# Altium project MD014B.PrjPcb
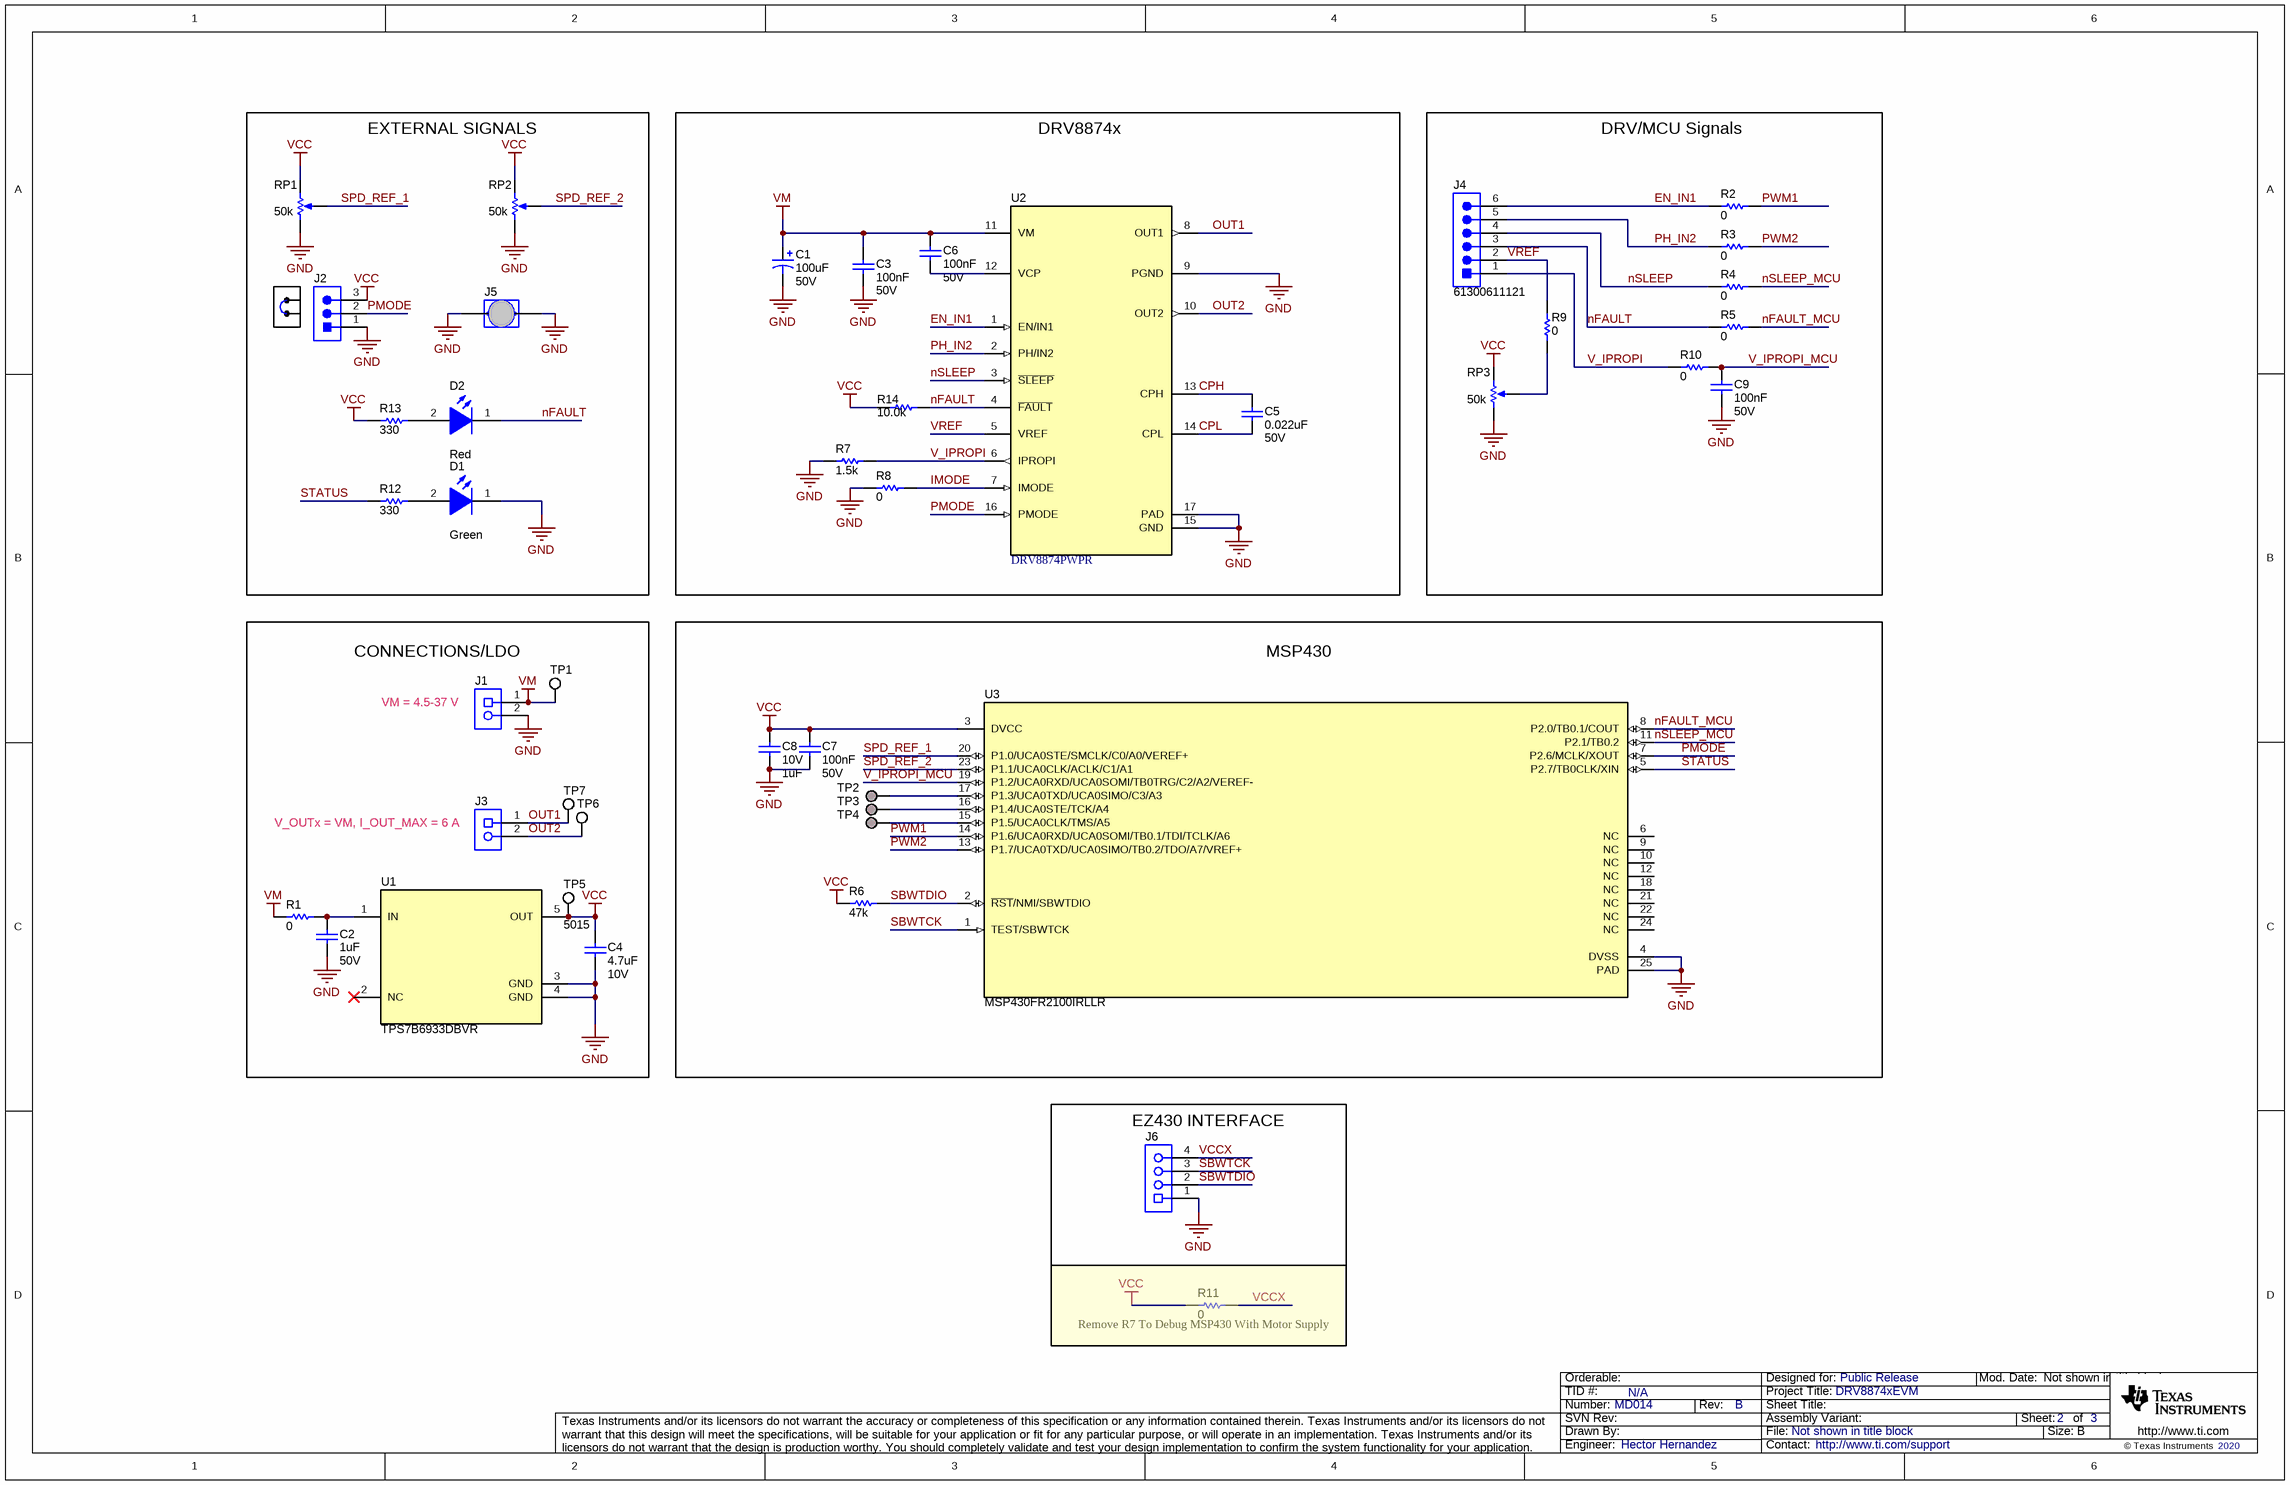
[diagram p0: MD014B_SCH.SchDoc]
CopyrightYear: 2020; PCB_Layout: Hector Hernandez; PCB_Rev: B; PRJ_Customer: Public Release; PRJ_Engineer: Hector Hernandez; PRJ_Number: MD014; PRJ_Title: DRV8874xEVM; SCH_Rev: B; TechSupport: http://www.ti.com/support; TID: N/A
2 sheets, 64 parts. Net scope: global (net labels, ports and power ports of the same name join across sheets).
Board file: MD014B_PCB.PcbDoc
Sheets:
  MD014B_SCH.SchDoc
  MD014B_Hardware.SchDoc

## Sheet MD014B_SCH.SchDoc
size 431 x 279 mm; Date: Not shown in title block; ApprovedBy: Not shown in title block; CheckedBy: Not shown in title block; Author: Not shown in title block; CompanyName: Not shown in title block; Engineer: Not shown in title block; Organization: Not shown in title block; Address1: Not shown in title block; Address2: Not shown in title block; Address3: Not shown in title block; Address4: Not shown in title block; DocumentNumber: 1; Revision: Use project parameter SCH_Rev; SheetNumber: 2; SheetTotal: 3; PageSetup: Record=PageOptions¦CenterHorizontal=True¦CenterVertical=True¦PrintScale=1.00¦XCorrection=1.00¦YCorrection=1.00¦PrintKind=0¦BorderSize=5000000¦LeftOffset=0¦BottomOffset=0¦Orientation=2¦PaperLength=1000¦PaperWidth=1000¦Scale=100¦PaperSource=15¦PrintQuality=600¦MediaType=1¦DitherType=10¦PaperKind=Letter¦PrintScaleMode=1

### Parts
C1  ValueDisplayed: 100uF  VDC_V: 50V  [BT_1000x1250]  (hidden comment: UBT1H101MPD1TD)
C2  ValueDisplayed: 1uF  VDC_V: 50V  [0805L]  (hidden comment: 885012207103)
C3  Cap_F: 100nF  VDC_V: 50V  [0603L]  (hidden comment: 885012206095)
C4  ValueDisplayed: 4.7uF  VDC_V: 10V  [0603L]  (hidden comment: C0603C475K8PACTU)
C5  ValueDisplayed: 0.022uF  VDC_V: 50V  [0603L]  (hidden comment: 885012206091)
C6  Cap_F: 100nF  VDC_V: 50V  [0603L]  (hidden comment: 885012206095)
C7  Cap_F: 100nF  VDC_V: 50V  [0603L]  (hidden comment: 885012206095)
C8  VDC_V: 10V  ValueDisplayed: 1uF  [0603L]  (hidden comment: 885012206026)
C9  Cap_F: 100nF  VDC_V: 50V  [0603L]  (hidden comment: 885012206095)
D1  value Green  [WL-SMCW_GREEN]  (hidden comment: 150060VS75000)
D2  value Red  [WL-SMCW_RED]  (hidden comment: 150060RS75000)
J1  CMP-0054828-1  [Wurth_691101710002]  (value not drawn)
J2  61300311121  [WURTH_61300311121]  (value not drawn)
J3  CMP-0054828-1  [Wurth_691101710002]  (value not drawn)
J4  61300611121  [WURTH_61300611121]
J5  D3082-05  [Harwin_D3082-05]  (value not drawn)
J6  851-43-004-20-001000  [CONN_851-43-004-20-001000]  (value not drawn)
R1  ValueDisplayed: 0  [0603L]  (hidden comment: ERJ-3GEY0R00V)
R2  ValueDisplayed: 0  [0603L]  (hidden comment: ERJ-3GEY0R00V)
R3  ValueDisplayed: 0  [0603L]  (hidden comment: ERJ-3GEY0R00V)
R4  ValueDisplayed: 0  [0603L]  (hidden comment: ERJ-3GEY0R00V)
R5  ValueDisplayed: 0  [0603L]  (hidden comment: ERJ-3GEY0R00V)
R6  ValueDisplayed: 47k  [0603L]  (hidden comment: CRCW060347K0JNEA)
R7  ValueDisplayed: 1.5k  [0603L]  (hidden comment: CRCW06031K50JNEA)
R8  ValueDisplayed: 0  [0603L]  (hidden comment: ERJ-3GEY0R00V)
R9  ValueDisplayed: 0  [0603L]  (hidden comment: ERJ-3GEY0R00V)
R10  ValueDisplayed: 0  [0603L]  (hidden comment: ERJ-3GEY0R00V)
R11  ValueDisplayed: 0  [0603L]  (hidden comment: ERJ-3GEY0R00V)
R12  ValueDisplayed: 330  [0603L]  (hidden comment: CRCW0603330RJNEA)
R13  ValueDisplayed: 330  [0603L]  (hidden comment: CRCW0603330RJNEA)
R14  ValueDisplayed: 10.0k  [0603L]  (hidden comment: ERA-3ARW103V)
RP1  value 50k  [Bourns_3352T]  (hidden comment: 3352T-1-503LF)
RP2  value 50k  [Bourns_3352T]  (hidden comment: 3352T-1-503LF)
RP3  value 50k  [Bourns_3352T]  (hidden comment: 3352T-1-503LF)
SH-J1  60900213421  [Wurth_60900213421]  (value not drawn)
TP1  5016  [Testpoint_Keystone_Compact]  (value not drawn)
TP2  TP_H0.45P0.75  [TP_H045P075]  (value not drawn)  (no BOM)
TP3  TP_H0.45P0.75  [TP_H045P075]  (value not drawn)  (no BOM)
TP4  TP_H0.45P0.75  [TP_H045P075]  (value not drawn)  (no BOM)
TP5  5015  [Testpoint_Keystone_Compact]
TP6  5016  [Testpoint_Keystone_Compact]  (value not drawn)
TP7  5016  [Testpoint_Keystone_Compact]  (value not drawn)
U1  TPS7B6933DBVR  [DBV0005A_N]
U2  DRV8874PWPR  [PWP0016J_N]
U3  MSP430FR2100IRLLR  [RLL0024A]

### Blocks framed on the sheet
EXTERNAL SIGNALS: D1 D2 J2 J5 R12 R13 RP1 RP2 SH-J1
DRV8874x: C1 C3 C5 C6 R7 R8 R14 U2
DRV/MCU Signals: C9 J4 R2-R5 R9 R10 RP3
CONNECTIONS/LDO: C2 C4 J1 J3 R1 TP1 TP5-TP7 U1
MSP430: C7 C8 R6 TP2-TP4 U3
EZ430 INTERFACE: J6
Remove R7 To Debug MSP430 With Motor Supply: R11

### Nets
GND: C1.2(-) C2.2 C3.2 C4.2 C7.2 C8.2 C9.2 D1.1(K) J1.2 J2.1 J5.1 J5.2 J6.1 R7.1 R8.1 RP1.1(CCW) RP2.1(CCW) RP3.1(CCW) U1.3(GND) U1.4(GND) U2.9(PGND) U2.15(GND) U2.17(PAD) U3.4(DVSS) U3.25(PAD)
VCC: C4.1 C7.1 C8.1 J2.3 R6.1 R11.1 R13.2 R14.1 RP1.3(CW) RP2.3(CW) RP3.3(CW) TP5.1 U1.5(OUT) U3.3(DVCC)
VM: C1.1(+) C3.1 C6.1 J1.1 R1.1 TP1.1 U2.11(VM)
CPH: C5.1 U2.13(CPH)
CPL: C5.2 U2.14(CPL)
EN_IN1: J4.6 R2.1 U2.1(EN/IN1)
IMODE: R8.2 U2.7(IMODE)
nFAULT: D2.1(K) J4.3 R5.1 R14.2 U2.4(~{FAULT})
nFAULT_MCU: R5.2 U3.8(P2.0/TB0.1/COUT)
nSLEEP: J4.4 R4.1 U2.3(~{SLEEP})
nSLEEP_MCU: R4.2 U3.11(P2.1/TB0.2)
OUT1: J3.1 TP7.1 U2.8(OUT1)
OUT2: J3.2 TP6.1 U2.10(OUT2)
PH_IN2: J4.5 R3.1 U2.2(PH/IN2)
PMODE: J2.2 U2.16(PMODE) U3.7(P2.6/MCLK/XOUT)
PWM1: R2.2 U3.14(P1.6/UCA0RXD/UCA0SOMI/TB0.1/TDI/TCLK/A6)
PWM2: R3.2 U3.13(P1.7/UCA0TXD/UCA0SIMO/TB0.2/TDO/A7/VREF+)
SBWTCK: J6.3 U3.1(TEST/SBWTCK)
SBWTDIO: J6.2 R6.2 U3.2(~{RST}/NMI/SBWTDIO)
SPD_REF_1: RP1.2(WIPER) U3.20(P1.0/UCA0STE/SMCLK/C0/A0/VEREF+)
SPD_REF_2: RP2.2(WIPER) U3.23(P1.1/UCA0CLK/ACLK/C1/A1)
STATUS: R12.2 U3.5(P2.7/TB0CLK/XIN)
V_IPROPI: J4.1 R7.2 R10.1 U2.6(IPROPI)
V_IPROPI_MCU: C9.1 R10.2 U3.19(P1.2/UCA0RXD/UCA0SOMI/TB0TRG/C2/A2/VEREF-)
VCCX: J6.4 R11.2
VREF: J4.2 R9.1 U2.5(VREF)
NetC2_1: C2.1 R1.2 U1.1(IN)
NetC6_2: C6.2 U2.12(VCP)
NetD1_2: D1.2(A) R12.1
NetD2_2: D2.2(A) R13.1
NetR9_2: R9.2 RP3.2(WIPER)
NetTP2_1: TP2.1 U3.17(P1.3/UCA0TXD/UCA0SIMO/C3/A3)
NetTP3_1: TP3.1 U3.16(P1.4/UCA0STE/TCK/A4)
NetTP4_1: TP4.1 U3.15(P1.5/UCA0CLK/TMS/A5)

Not connected (* = marked no-connect by the designer): U1 2(NC)*; U3 6(NC) 9(NC) 10(NC) 12(NC) 18(NC) 21(NC) 22(NC) 24(NC)

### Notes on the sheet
- (near J1) VM = 4.5-37 V
- (near J3) V_OUTx = VM, I_OUT_MAX = 6 A

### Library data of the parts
C1 = CMP-0009918-2: CAP, AL, 100 uF, 50 V, +/- 20%, TH; Manufacturer: Nichicon; Polarized: Y; CompType: Capacitor; Value: 100uF; U/M: EA; Cap_F: 100µF; Value1: Unknown; IRMS_A: 5.55dA; TaMin_C: -40°C; TaMax_C: 125°C; Cap_Case: 10x12.5mm; SizeAreaWB_mm2: 144; SizeArea_mm2: 100; SizeX_mm: 10; SizeZ_mm: 14.5; AEC Category: Q200; AEC Qualified: N
C2 = CMP-0007696-2: CAP, CERM, 1 uF, 50 V, +/- 10%, X7R, 0805; Manufacturer: Wurth Elektronik; Polarized: N; CompType: Capacitor; Value: 1uF; U/M: EA; Cap_F: 1µF; Value1: Unknown; TaMin_C: -55°C; TaMax_C: 125°C; Cap_Case: 0805; SizeArea_mm2: 2.5; SizeAreaWB_mm2: 6.75; SizeX_mm: 2; SizeY_mm: 1.25; SizeZ_mm: 1.45; AEC Category: Q200
C3 C6 C7 C9 = CMP-0006837-4: CAP, CERM, 0.1 uF, 50 V, +/- 10%, X7R, 0603; Manufacturer: Wurth Elektronik; Polarized: N; Value: 0.1uF; U/M: EA; Value1: Unknown; TaMin_C: -55°C; TaMax_C: 125°C; Cap_Case: 0603; SizeArea_mm2: 1.28; SizeAreaWB_mm2: 4.68; SizeX_mm: 1.6; SizeY_mm: 0.8; SizeZ_mm: 1; AEC Category: Q200
C4 = CMP-0006949-5: CAP, CERM, 4.7 uF, 10 V, +/- 10%, X5R, 0603; Manufacturer: Kemet; Polarized: N; CompType: Capacitor; Value: 4.7uF; U/M: EA; Cap_F: 4.7µF; ESR_ohm: 6m; Value1: 0.006 ohm; IRMS_A: 7.24A; TaMin_C: -55°C; TaMax_C: 85°C; Cap_Case: 0603; SizeArea_mm2: 1.28; SizeAreaWB_mm2: 4.68; SizeX_mm: 1.6; SizeY_mm: 0.8; SizeZ_mm: 1; AEC Category: Q200
C5 = CMP-0006836-4: CAP, CERM, 0.022 uF, 50 V, +/- 10%, X7R, 0603; Manufacturer: Wurth Elektronik; Polarized: N; U/M: EA; Cap_F: 22nF; Value1: Unknown; TaMin_C: -55°C; TaMax_C: 125°C; Cap_Case: 0603; SizeArea_mm2: 1.28; SizeAreaWB_mm2: 4.68; SizeX_mm: 1.6; SizeY_mm: 0.8; SizeZ_mm: 1; AEC Category: Q200
C8 = CMP-0064932-4: CAP, CERM, 1 uF, 10 V,+/- 10%, X7R, 0603; Manufacturer: Wurth Elektronik; TaMin_C: -55°C; Polarized: N; SizeAreaWB_mm2: 4.68; Value1: Unknown; U/M: EA; Value: 1uF; TaMax_C: 125°C; SizeZ_mm: 1; SizeX_mm: 1.6; SizeY_mm: 0.8; Cap_Case: 0603; SizeArea_mm2: 1.28; CompType: Capacitor; Cap_F: 1µF; AEC Category: Q200
D1 = CMP-0002894-1: LED, Green, SMD; Manufacturer: Wurth Elektronik; Type: AlInGaP; Vf_V: 2V; Io_A: 20mA; Value1: W; U/M: EA
D2 = CMP-0002947-2: LED, Red, SMD; Manufacturer: Wurth Elektronik; Type: AlInGaP; Vf_V: 2V; Io_A: 30mA; Vr_V: 5V; Tjmax_C: 85°C; Power_TotalModule: 72mW; Value1: 0.072W; Angle: 140; U/M: EA
J1 J3 = CMP-0054828-1: Terminal Block, 5 mm, 2x1, Tin, TH; PartNumber: 691 101 710 002; Manufacturer: Wurth Elektronik; CNHeader: FALSE; Green_Lifecycle: Active; Green_REACh: Passed; CT: TRUE
J2 = CMP-0054796-1: Header, 2.54 mm, 3x1, Gold, TH; Manufacturer: Wurth Elektronik; Green_Lifecycle: Active; Green_REACh: Passed; CNHeader: TRUE; CT: FALSE
J4 = CMP-0054801-1: Header, 2.54 mm, 6x1, Gold, TH; Manufacturer: Wurth Elektronik; CNHeader: TRUE; CT: FALSE
J5 = CMP-0075110-1: 1mm Uninsulated Shorting Plug, 10.16mm spacing, TH; Manufacturer: Harwin; CompType: Jumper Wire; Green_Lifecycle: Active; Green_REACh: Passed; CNHeader: False
J6 = CMP-0055060-1: SOCKET .050" GRID SIP 4 POS R/A, TH; Manufacturer: Mill-Max; CompType: Socket Strip; CNHeader: FALSE; CT: TRUE; Gender: Female; Green_Lifecycle: Active; Green_REACh: Passed
R1-R5 R8-R11 = CMP-0025874-3: RES, 0, 5%, 0.1 W, 0603; Manufacturer: Panasonic; Value: 0; Value_Code: 0000; Power_W: 100mW; Value2: 0.1W; VDC_V: 50V; TempCo: 600 ppm/C; EIA_Code: E24; U/M: EA; SizeArea_mm2: 1.28; SizeX_mm: 1.6; SizeY_mm: 0.8; SizeZ_mm: 1; AEC Category: Q200
R6 = CMP-0025814-4: RES, 47 k, 5%, 0.1 W, AEC-Q200 Grade 0, 0603; Manufacturer: Vishay-Dale; Value: 47k; Value_Code: 47k0; Power_W: 100mW; Value2: 0.1W; VDC_V: 75V; TempCo: 200 ppm/C; EIA_Code: E24; AEC Category: Q200; AEC Grade: 0; AEC Qualified: Y; SizeArea_mm2: 1.28; SizeX_mm: 1.6; SizeY_mm: 0.8; SizeZ_mm: 1
R7 = CMP-0025733-4: RES, 1.5 k, 5%, 0.1 W, AEC-Q200 Grade 0, 0603; Manufacturer: Vishay-Dale; Value: 1.5k; Value_Code: 1k50; Power_W: 100mW; Value2: 0.1W; VDC_V: 75V; TempCo: 200 ppm/C; SizeArea_mm2: 1.28; SizeX_mm: 1.6; SizeY_mm: 0.8; SizeZ_mm: 1; EIA_Code: E24; AEC Category: Q200; AEC Qualified: Y; AEC Grade: 0
R12 R13 = CMP-0025785-4: RES, 330, 5%, 0.1 W, AEC-Q200 Grade 0, 0603; Manufacturer: Vishay-Dale; Value: 330; Value_Code: 330R; Power_W: 100mW; Value2: 0.1W; VDC_V: 75V; TempCo: 200 ppm/C; EIA_Code: E24; AEC Category: Q200; AEC Grade: 0; AEC Qualified: Y; SizeArea_mm2: 1.28; SizeX_mm: 1.6; SizeY_mm: 0.8; SizeZ_mm: 1
R14 = CMP-0086251-1: RES, 10.0 k, 0.05%, 0.1 W, AEC-Q200 Grade 0, 0603; Manufacturer: Panasonic; Res_ohm: 10k; Value: 10.0k; SizeY_mm: 0.8; SizeArea_mm2: 1.28; SizeAreaWB_mm2: 4.68; AEC Grade: 0; Power_W: 100mW; SizeX_mm: 1.6; Value2: 0.1W; Value_Code: 10k0; SizeZ_mm: 1; AEC Qualified: Y; AEC Category: Q200; TempCo: 10 ppm/C
RP1-RP3 = CMP-0001777-2: Trimming Potentiometer, 50K, 0.5W, TH; Manufacturer: Bourns; CompType: Trimmer
SH-J1 = CMP-0003761-1: Shunt, 2.54mm, Gold, Black; Manufacturer: Wurth Elektronik
TP1 TP5-TP7 = CMP-0055153-1: Test Point, Compact, SMT; Manufacturer: Keystone; Green_Lifecycle: Active; Green_REACh: Passed; CNHeader: FALSE; CT: TRUE
TP2-TP4 = CMP-0003719-1: Testpoint; Manufacturer: Texas Instruments; CompType: Pad
U1 = CMP-0077328-2: 40-V Ultralow-Iq Low-Dropout Regulator, DBV0005A (SOT-23-5); Manufacturer: Texas Instruments; SizeArea_mm2: 8.12; CompType: IC; SizeAreaWB_mm2: 14.82; SizeY_mm: 2.9; SizeZ_mm: 1.45; SizeX_mm: 2.8; AEC Category: Q200; AEC Qualified: N
U2 = CMP-0081845-1: H-Bridge Motor Drivers With Integrated Current Sense and Regulation, PWP0016J (HTSSOP-16); Alternate Manufacturer: Texas Instruments; SizeAreaWB_mm2: 58.8; SizeZ_mm: 1.2; SizeX_mm: 6.4; SizeY_mm: 5; SizeArea_mm2: 32; CompType: IC; AEC Qualified: N; AEC Category: Q200
U3 = CMP-0080370-1: 16 MHz Ultra-Low-Power Microcontroller With 1 KB FRAM, 0.5 KB SRAM, 12 IO, 8 ch 10-bit ADC, RLL0024A (VQFN-24); Manufacturer: Texas Instruments; Alternate PartNumber: MSP430FR2100IRLLT; SizeAreaWB_mm2: 16; SizeArea_mm2: 9; AEC Qualified: N; AEC Category: Q200; SizeZ_mm: 1; SizeY_mm: 3; CompType: IC

## Sheet MD014B_Hardware.SchDoc
size 431 x 279 mm; Date: Not shown in title block; ApprovedBy: Not shown in title block; CheckedBy: Not shown in title block; Author: Not shown in title block; CompanyName: Not shown in title block; Engineer: Not shown in title block; Organization: Not shown in title block; Address1: Not shown in title block; Address2: Not shown in title block; Address3: Not shown in title block; Address4: Not shown in title block; DocumentNumber: 1; Revision: Use project parameter SCH_Rev; SheetNumber: 2; SheetTotal: 3; PageSetup: Record=PageOptions¦CenterHorizontal=True¦CenterVertical=True¦PrintScale=1.00¦XCorrection=1.00¦YCorrection=1.00¦PrintKind=0¦BorderSize=5000000¦LeftOffset=0¦BottomOffset=0¦Orientation=2¦PaperLength=1000¦PaperWidth=1000¦Scale=100¦PaperSource=15¦PrintQuality=600¦MediaType=1¦DitherType=10¦PaperKind=Letter¦PrintScaleMode=1
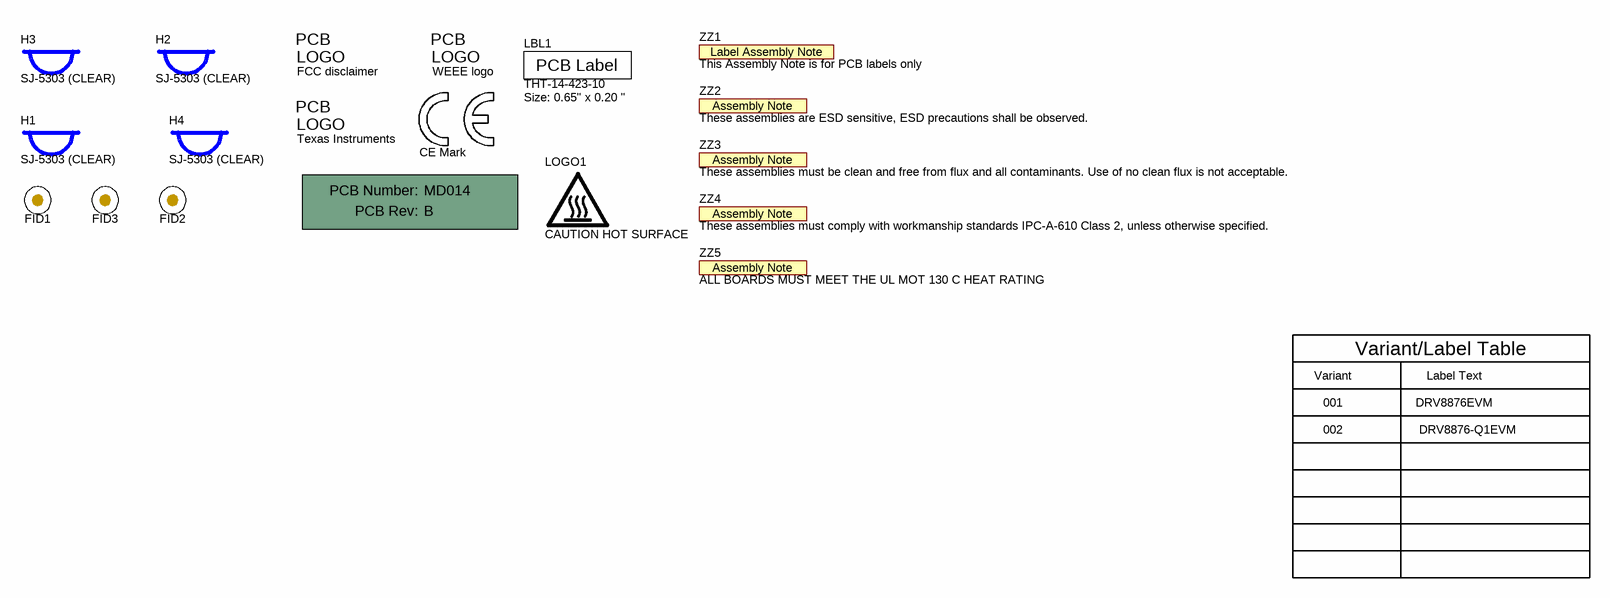
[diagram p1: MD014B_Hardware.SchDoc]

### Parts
!PCB1  Printed Circuit Board  (value not drawn)  (mechanical)
FID1  Fiducial  [Fiducial10-20]  (value not drawn)
FID2  Fiducial  [Fiducial10-20]  (value not drawn)
FID3  Fiducial  [Fiducial10-20]  (value not drawn)
H1  SJ-5303 (CLEAR)  [Bumpon_SJ5003Transparent]
H2  SJ-5303 (CLEAR)  [Bumpon_SJ5003Transparent]
H3  SJ-5303 (CLEAR)  [Bumpon_SJ5003Transparent]
H4  SJ-5303 (CLEAR)  [Bumpon_SJ5003Transparent]
LBL1  THT-14-423-10  Note: Size: 0.65" x 0.20 "  [Label_650x200]
LOGO1  CAUTION HOT SURFACE  [IEC_HotSurface_Small]  (no BOM)
Logo2  Texas Instruments  [TI_Stacked_Overlay_Small]  (no BOM)
Logo3  FCC disclaimer  [FCC_disclaimer]  (no BOM)
Logo4  CE Mark  [CE_Mark_5mm]  (no BOM)
Logo5  WEEE logo  [WEEE_Minimum]  (no BOM)
ZZ1  This Assembly Note is for PCB labels only  [AssemblyNoteLabel]  (no BOM)
ZZ2  These assemblies are ESD sensitive, ESD precautions shall be observed.  [AssemblyNote]  (no BOM)
ZZ3  These assemblies must be clean and free from flux and all contaminants. Use of no clean flux is not acceptable.  [AssemblyNote]  (no BOM)
ZZ4  These assemblies must comply with workmanship standards IPC-A-610 Class 2, unless otherwise specified.  [AssemblyNote]  (no BOM)
ZZ5  ALL BOARDS MUST MEET THE UL MOT 130 C HEAT RATING  [AssemblyNote]  (no BOM)

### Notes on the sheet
- Variant/Label Table
- Variant
- 001
- 002
- Label Text
- DRV8876EVM
- DRV8876-Q1EVM

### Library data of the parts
!PCB1 = CMP-0003618-2: PartNumber: MD014; Manufacturer: Any; CompType: PCB
FID1-FID3 = CMP-0077181-1: Fiducial mark.  There is nothing to buy or mount.
H1-H4 = CMP-0003620-1: Bumpon, Hemisphere, 0.44 X 0.20, Clear; Manufacturer: 3M
LBL1 = CMP-0003625-1: Thermal Transfer Printable Labels, 0.650" W x 0.200" H - 10,000 per roll; Manufacturer: Brady; CompType: Label
LOGO1 = CMP-0074837-1: IEC 61010-1 Hot Surface Warning; SymbolCreator: a0412235
Logo2 = CMP-0074838-1: Texas Instrument Corporate Signature; SymbolCreator: a0412235; Lib Reference: TI_Logo; Library Reference: Logo
Logo3 = CMP-0074847-1: FCC_disclaimer; Library Reference: Logo
Logo4 = CMP-0074844-1: SymbolCreator: a0412235
Logo5 = CMP-0074769-1
ZZ1 = CMP-0003616-3
ZZ2 = CMP-0077236-1
ZZ3 = CMP-0077237-1
ZZ4 = CMP-0077238-1
ZZ5 = CMP-0077238-1: These assemblies must comply with workmanship standards IPC-A-610 Class 2, unless otherwise specified.

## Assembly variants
001: not fitted C9 FID1 FID2 FID3
002: not fitted C9 FID1 FID2 FID3; alternate parts U2 -> CMP-0084452-1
